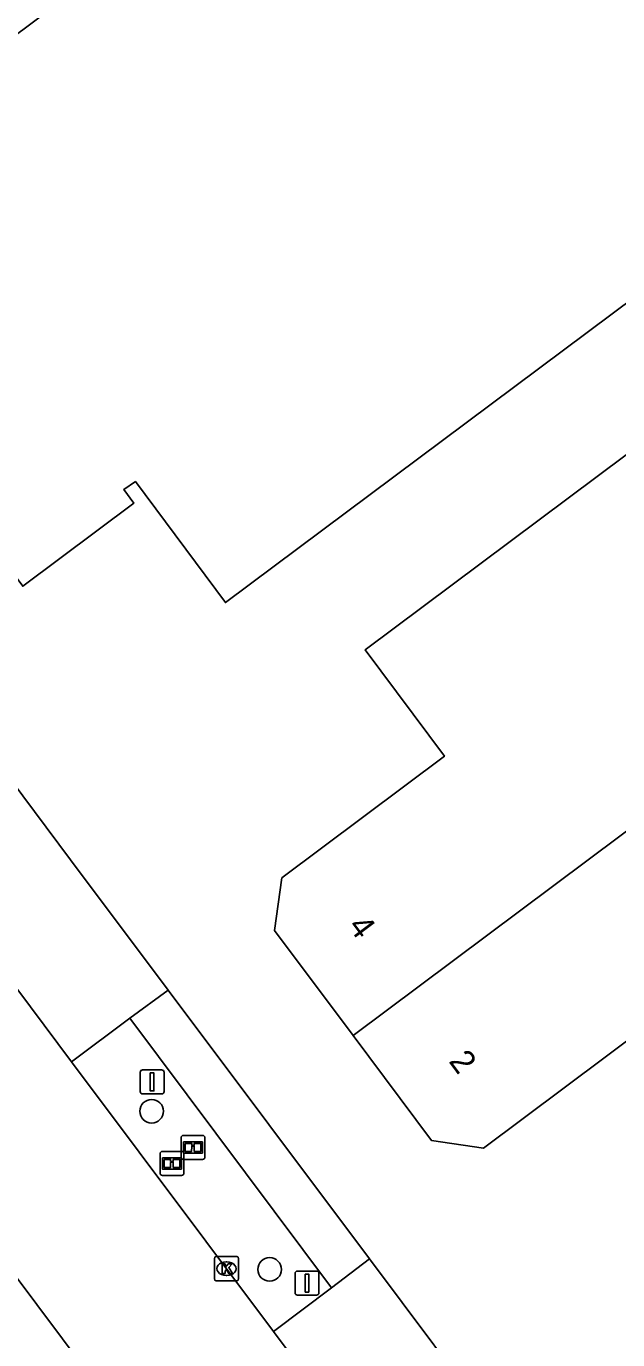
# Model space of a CAD drawing. Extents: x 156651 to 158072, y 387631 to 388990.
# Drawn here: x 157762.6 to 157787.1, y 388530.3 to 388584.8 of the extents above; entities that cross this region are included whole.
import ezdxf

# ---------------------------------------------------------------- set-up
doc = ezdxf.new("R2010")
doc.units = 0
for name, color, linetype in [('IMGEO_Boom', 7, 'Continuous'), ('IMGEO_Informatiebord', 7, 'Continuous'), ('IMGEO_Kolk', 7, 'Continuous'), ('IMGEO_Pand', 7, 'Continuous'), ('IMGEO_Pand_nummerreeks', 7, 'Continuous'), ('IMGEO_Rijbaan_lokaal_gesloten', 7, 'Continuous'), ('IMGEO_Verkeersbordpaal', 7, 'Continuous'), ('IMGEO_Voetpad_open', 7, 'Continuous')]:
    doc.layers.add(name, color=color, linetype=linetype)

msp = doc.modelspace()

# ---------------------------------------------------------------- linework, layer by layer
at = {"layer": 'IMGEO_Boom'}
for centre in [(157767.774, 388539.744), (157772.671, 388533.178)]:
    msp.add_circle(centre, 0.489, dxfattribs=at)
at = {"layer": 'IMGEO_Informatiebord'}
for p, q in [((157769.094, 388538.741), (157769.884, 388538.741)), ((157769.884, 388538.741), (157769.094, 388538.741)), ((157768.994, 388537.841), (157768.994, 388538.641)), ((157768.994, 388538.641), (157768.994, 388537.841)), ((157769.984, 388538.641), (157769.984, 388537.841)), ((157769.984, 388537.841), (157769.984, 388538.641)), ((157768.121, 388537.177), (157768.121, 388537.977)), ((157768.121, 388537.977), (157768.121, 388537.177)), ((157768.221, 388538.077), (157769.011, 388538.077)), ((157769.011, 388538.077), (157768.221, 388538.077)), ((157769.884, 388537.741), (157769.094, 388537.741)), ((157769.094, 388537.741), (157769.884, 388537.741)), ((157769.111, 388537.977), (157769.111, 388537.177)), ((157769.111, 388537.177), (157769.111, 388537.977)), ((157769.011, 388537.077), (157768.221, 388537.077)), ((157768.221, 388537.077), (157769.011, 388537.077))]:
    msp.add_line(p, q, dxfattribs=at)
for points in [[(157769.095, 388538.473), (157769.883, 388538.473), (157769.883, 388538.009), (157769.095, 388538.009), (157769.095, 388538.473)], [(157769.16, 388538.408), (157769.16, 388538.074), (157769.435, 388538.074), (157769.436, 388538.287), (157769.54, 388538.288), (157769.541, 388538.074), (157769.818, 388538.074), (157769.818, 388538.408), (157769.542, 388538.408), (157769.542, 388538.328), (157769.436, 388538.328), (157769.436, 388538.408), (157769.16, 388538.408)], [(157768.222, 388537.809), (157769.01, 388537.809), (157769.01, 388537.345), (157768.222, 388537.345), (157768.222, 388537.809)], [(157768.287, 388537.744), (157768.287, 388537.41), (157768.562, 388537.41), (157768.563, 388537.623), (157768.667, 388537.624), (157768.668, 388537.41), (157768.945, 388537.41), (157768.945, 388537.744), (157768.669, 388537.744), (157768.669, 388537.664), (157768.563, 388537.664), (157768.563, 388537.744), (157768.287, 388537.744)]]:
    msp.add_lwpolyline(points, dxfattribs=at)
for centre, start, end in [((157769.094, 388538.641), 90, 180), ((157769.094, 388538.641), 90, 180), ((157769.884, 388538.641), 0, 90), ((157769.884, 388538.641), 360, 90), ((157768.221, 388537.977), 90, 180), ((157768.221, 388537.977), 90, 180), ((157769.094, 388537.841), 180, 270), ((157769.094, 388537.841), 180, 270), ((157769.011, 388537.977), 0, 90), ((157769.011, 388537.977), 360, 90), ((157769.884, 388537.841), 270, 0), ((157769.884, 388537.841), 270, 0), ((157768.221, 388537.177), 180, 270), ((157768.221, 388537.177), 180, 270), ((157769.011, 388537.177), 270, 0), ((157769.011, 388537.177), 270, 0)]:
    msp.add_arc(centre, 0.1, start, end, dxfattribs=at)
at = {"layer": 'IMGEO_Kolk'}
for p, q in [((157770.379, 388532.783), (157770.379, 388533.635)), ((157770.454, 388533.709), (157771.306, 388533.709)), ((157770.867, 388533.489), (157770.892, 388533.489)), ((157771.38, 388533.635), (157771.38, 388532.783)), ((157771.306, 388532.709), (157770.454, 388532.709)), ((157770.89, 388532.929), (157770.865, 388532.929))]:
    msp.add_line(p, q, dxfattribs=at)
for points in [[(157770.379, 388532.783), (157770.379, 388533.635)], [(157770.454, 388533.709), (157771.306, 388533.709)], [(157770.7, 388533.409), (157770.823, 388533.409), (157770.823, 388533.258), (157770.953, 388533.409), (157771.117, 388533.409), (157770.971, 388533.258), (157771.124, 388533.009), (157770.972, 388533.009), (157770.887, 388533.173), (157770.823, 388533.106), (157770.823, 388533.009), (157770.7, 388533.009), (157770.7, 388533.409)], [(157771.38, 388533.635), (157771.38, 388532.783)], [(157771.306, 388532.709), (157770.454, 388532.709)]]:
    msp.add_lwpolyline(points, dxfattribs=at)
for centre, start, end in [((157770.456, 388533.633), 91.552, 178.448), ((157770.456, 388533.633), 91.552, 178.448), ((157771.304, 388533.633), 1.552, 88.448), ((157771.304, 388533.633), 1.552, 88.448), ((157770.456, 388532.785), 181.552, 268.448), ((157770.456, 388532.785), 181.552, 268.448), ((157771.304, 388532.785), 271.552, 358.448), ((157771.304, 388532.785), 271.552, 358.448)]:
    msp.add_arc(centre, 0.0765, start, end, dxfattribs=at)
for centre, major_axis, ratio, start_param, end_param in [((157770.866, 388533.209), (-0.387, 0.002), 0.722429, 4.712389, 7.853982), ((157770.891, 388533.209), (-0.39, 0.002), 0.717154, 1.570796, 4.712389)]:
    msp.add_ellipse(centre, major_axis=major_axis, ratio=ratio, start_param=start_param, end_param=end_param, dxfattribs=at)
at = {"layer": 'IMGEO_Pand'}
for points in [[(157795.49, 388609.351), (157800.933, 388602.076), (157809.912, 388590.06), (157770.834, 388560.859), (157767.103, 388565.883), (157766.618, 388565.55), (157767.037, 388564.99), (157762.428, 388561.536), (157758.085, 388567.345), (157758.389, 388567.572), (157758.103, 388567.958), (157757.203, 388567.285), (157755.975, 388568.927), (157756.875, 388569.597), (157756.586, 388569.987), (157756.282, 388569.759), (157751.946, 388575.556), (157756.546, 388578.995), (157756.971, 388578.426), (157757.429, 388578.783), (157756.406, 388580.153), (157795.49, 388609.351)], [(157776.132, 388542.884), (157772.876, 388547.242), (157773.177, 388549.426), (157779.926, 388554.478), (157776.634, 388558.897), (157810.284, 388584.036), (157817.772, 388574.014)], [(157817.772, 388574.014), (157825.259, 388563.992), (157791.614, 388538.852), (157788.3, 388543.26), (157781.551, 388538.207), (157779.382, 388538.534), (157776.132, 388542.884)], [(157776.132, 388542.884), (157817.772, 388574.014)]]:
    msp.add_lwpolyline(points, dxfattribs=at)
at = {"layer": 'IMGEO_Rijbaan_lokaal_gesloten'}
for points in [[(157764.445, 388541.799), (157760.423, 388547.176), (157754.398, 388555.23)], [(157746.116, 388554.3), (157786.233, 388500.645)], [(157772.827, 388530.595), (157764.445, 388541.799)], [(157778.233, 388523.368), (157772.827, 388530.595)]]:
    msp.add_lwpolyline(points, dxfattribs=at)
at = {"layer": 'IMGEO_Verkeersbordpaal'}
for p, q in [((157767.399, 388541.46), (157768.189, 388541.46)), ((157768.189, 388541.46), (157767.399, 388541.46)), ((157767.299, 388540.56), (157767.299, 388541.36)), ((157767.299, 388541.36), (157767.299, 388540.56)), ((157768.289, 388541.36), (157768.289, 388540.56)), ((157768.289, 388540.56), (157768.289, 388541.36)), ((157768.189, 388540.46), (157767.399, 388540.46)), ((157767.399, 388540.46), (157768.189, 388540.46)), ((157773.727, 388532.209), (157773.727, 388533.009)), ((157773.727, 388533.009), (157773.727, 388532.209)), ((157773.827, 388533.109), (157774.617, 388533.109)), ((157774.617, 388533.109), (157773.827, 388533.109)), ((157774.717, 388533.009), (157774.717, 388532.209)), ((157774.717, 388532.209), (157774.717, 388533.009)), ((157774.617, 388532.109), (157773.827, 388532.109)), ((157773.827, 388532.109), (157774.617, 388532.109))]:
    msp.add_line(p, q, dxfattribs=at)
for points in [[(157767.719, 388541.335), (157767.869, 388541.335), (157767.869, 388540.585), (157767.719, 388540.585), (157767.719, 388541.335)], [(157774.147, 388532.984), (157774.297, 388532.984), (157774.297, 388532.234), (157774.147, 388532.234), (157774.147, 388532.984)]]:
    msp.add_lwpolyline(points, dxfattribs=at)
for centre, start, end in [((157767.399, 388541.36), 90, 180), ((157767.399, 388541.36), 90, 180), ((157768.189, 388541.36), 0, 90), ((157768.189, 388541.36), 360, 90), ((157767.399, 388540.56), 180, 270), ((157767.399, 388540.56), 180, 270), ((157768.189, 388540.56), 270, 0), ((157768.189, 388540.56), 270, 0), ((157773.827, 388533.009), 90, 180), ((157773.827, 388533.009), 90, 180), ((157774.617, 388533.009), 0, 90), ((157774.617, 388533.009), 360, 90), ((157773.827, 388532.209), 180, 270), ((157773.827, 388532.209), 180, 270), ((157774.617, 388532.209), 270, 0), ((157774.617, 388532.209), 270, 0)]:
    msp.add_arc(centre, 0.1, start, end, dxfattribs=at)
at = {"layer": 'IMGEO_Voetpad_open'}
for points in [[(157758.423, 388558.206), (157764.403, 388550.183), (157768.457, 388544.772)], [(157766.867, 388543.606), (157768.457, 388544.772)], [(157768.457, 388544.772), (157776.821, 388533.611)], [(157764.445, 388541.799), (157766.867, 388543.606)], [(157775.238, 388532.42), (157766.867, 388543.606)], [(157776.821, 388533.611), (157775.238, 388532.42)], [(157776.821, 388533.611), (157782.202, 388526.417)], [(157775.238, 388532.42), (157772.827, 388530.595)]]:
    msp.add_lwpolyline(points, dxfattribs=at)

# ---------------------------------------------------------------- texts
at = {"layer": 'IMGEO_Pand_nummerreeks'}
for s, p in [('4', (157775.891, 388547.417)), ('2', (157780.077, 388541.814))]:
    msp.add_text(s, height=1, rotation=306.7645, dxfattribs=at).set_placement(p)

doc.saveas('drawing.dxf')
